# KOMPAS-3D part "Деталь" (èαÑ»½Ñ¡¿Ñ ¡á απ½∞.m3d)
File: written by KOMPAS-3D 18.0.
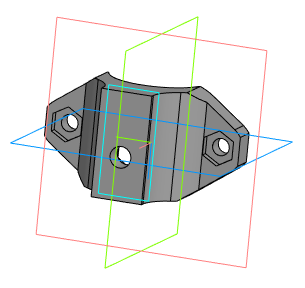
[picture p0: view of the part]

Document properties: Автор: Пользователь Windows; Полное имя файла: F:\Модели\Мех детали\Велосипед\Крепление фонаря\2\Крепление на руль.m3d

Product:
- Part/product: Деталь
    Масса: 0.056758

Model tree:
1. Эскиз:1
2. Элемент выдавливания:1
     Расстояние 1 = 10; Расстояние 2 = 15
3. Смещенная плоскость:1  (with: Элемент выдавливания:1)
     Расстояние = 5
4. Эскиз:2  (with: Элемент выдавливания:1)
5. Элемент выдавливания:2
     Расстояние 2 = 10
6. Эскиз:3  (with: Элемент выдавливания:2)
7. Элемент выдавливания:3
     Расстояние 2 = 10
8. Эскиз:4  (with: Элемент выдавливания:1)
9. Элемент выдавливания:4
     Расстояние 2 = 6
10. Эскиз:5  (with: Элемент выдавливания:4)
11. Элемент выдавливания:5  (with: Элемент выдавливания:4)
     Расстояние 2 = 2; Смещение 2 = 4
12. Скругление:1  (with: Элемент выдавливания:1)
     Радиус = 4
13. Скругление:2  (with: Элемент выдавливания:1)
     Радиус = 10
14. Эскиз:6  (with: Элемент выдавливания:1, Элемент выдавливания:2, Элемент выдавливания:5)
15. Элемент выдавливания:6
     Расстояние 2 = 20.5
